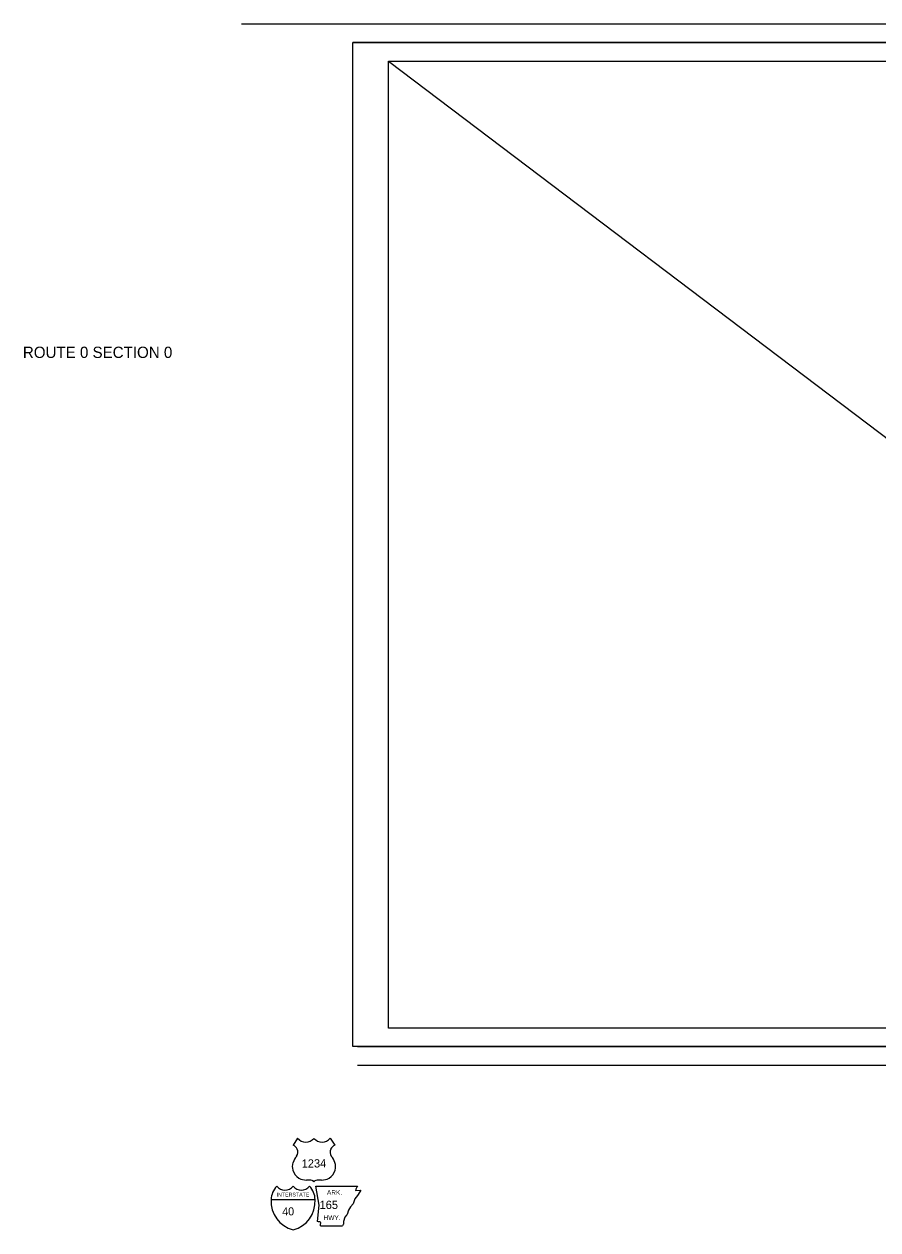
# Model space of a CAD drawing. Extents: x 21307 to 29830, y 1322443 to 1332359.
# Drawn here: x 23110 to 24924, y 1325020 to 1327582 of the extents above; entities that cross this region are included whole.
import ezdxf

# ---------------------------------------------------------------- set-up
doc = ezdxf.new("R2010")
doc.units = 0
doc.layers.add('R_Draft', color=7, linetype='Continuous')
doc.layers.add('R_No Plot', color=7, linetype='Continuous')

msp = doc.modelspace()

# ---------------------------------------------------------------- linework, layer by layer
at = {"layer": 'R_Draft'}
for p, q in [((27081.9, 1327581.7), (23572.1, 1327581.7)), ((27081.9, 1327542.3), (23808.3, 1327542.3)), ((23883.9, 1327502.8), (27045.7, 1327502.8)), ((23883.9, 1325448.4), (23883.9, 1327502.8)), ((27045.7, 1325448.4), (23883.9, 1325448.4)), ((23818.2, 1325409), (27091.7, 1325409)), ((23818.2, 1325369.6), (27091.7, 1325369.6)), ((23691, 1325214.2), (23681.7, 1325199.7)), ((23760.5, 1325214.2), (23769.9, 1325199.7)), ((23730, 1325112.4), (23818.2, 1325112.4)), ((23736.6, 1325072.2), (23730, 1325112.4)), ((23818.1, 1325092.3), (23812.7, 1325085.5)), ((23813.7, 1325103.6), (23825.3, 1325104.3)), ((23822.9, 1325100.5), (23818.1, 1325092.3)), ((23825.3, 1325104.3), (23822.9, 1325100.5)), ((23634.9, 1325084), (23728.2, 1325084)), ((23733.2, 1325037.1), (23736.6, 1325072.2)), ((23803.1, 1325068.4), (23799, 1325061.3)), ((23808.9, 1325074.6), (23803.1, 1325068.4)), ((23810.6, 1325079.4), (23808.9, 1325074.6)), ((23812.7, 1325085.5), (23810.6, 1325079.4)), ((23791.5, 1325046.9), (23788.5, 1325037.7)), ((23795.2, 1325050.7), (23791.5, 1325046.9)), ((23795.1, 1325050.6), (23796, 1325052.1)), ((23799, 1325061.3), (23796, 1325052.1)), ((23739.6, 1325028.5), (23786.1, 1325028.5)), ((23788.4, 1325032.1), (23786.1, 1325028.5)), ((23788.5, 1325037.7), (23788.4, 1325031.8))]:
    msp.add_line(p, q, dxfattribs=at)
for centre, radius, start, end in [((23669.5, 1325178.7), 24.3, 30.7809, 59.9883), ((23708.5, 1325228.8), 22.7, 220.075, 319.6701), ((23743.1, 1325228.8), 22.7, 220.3299, 319.925), ((23782.1, 1325178.7), 24.3, 120.0117, 149.2191), ((23718.4, 1325151), 38.8, 138.9565, 162.6913), ((23674.8, 1325185.1), 16.6, 328.8105, 21.2108), ((23776.8, 1325185.1), 16.6, 158.7892, 211.1895), ((23733.2, 1325151), 38.8, 17.3087, 41.0435), ((23705.5, 1325154.2), 25.7, 160.9576, 197.3819), ((23709.7, 1325154.3), 29.7, 195.1074, 237.1312), ((23741.9, 1325154.3), 29.7, 302.8688, 344.8926), ((23746, 1325154.2), 25.7, 342.6181, 19.0424), ((23710.3, 1325163.6), 38.1, 244.0771, 269.5779), ((23711.2, 1325055.7), 69.8, 81.1942, 90.9539), ((23719.9, 1325118.3), 6.69, 28.0342, 72.9864), ((23731.7, 1325118.3), 6.69, 107.0136, 151.9658), ((23740.4, 1325055.7), 69.8, 89.0461, 98.8058), ((23741.3, 1325163.6), 38.1, 270.4221, 295.9229), ((23675, 1325083.8), 40.1, 134.733, 179.7351), ((23664.2, 1325127), 22.7, 220.075, 319.6701), ((23698.9, 1325127), 22.7, 220.3299, 319.925), ((23688, 1325083.8), 40.1, 0.2649, 45.267), ((23696.9, 1325079.8), 62.1, 176.0938, 255.7023), ((23666.2, 1325079.8), 62.1, 284.2977, 3.9062)]:
    msp.add_arc(centre, radius, start, end, dxfattribs=at)
for points in [[(23818.2, 1325112.4), (23817.1, 1325110.1), (23815.1, 1325107.7), (23814.7, 1325104.3), (23813.7, 1325103.6)], [(23739.6, 1325028.5), (23740, 1325032.3), (23740.3, 1325034.7), (23733.2, 1325037.1)]]:
    msp.add_spline(points, degree=3, dxfattribs=at)
at = {"layer": 'R_No Plot'}
msp.add_line((23883.9, 1327502.8), (25205.3, 1326503), dxfattribs=at)
msp.add_lwpolyline([(23808.3, 1327542.3), (27091.7, 1327542.3), (27091.7, 1325409), (23808.3, 1325409)], close=True, dxfattribs=at)

# ---------------------------------------------------------------- texts
at = {"layer": 'R_Draft'}
for s, height, p in [('ROUTE 0 SECTION 0', 24, (23107.3, 1326872.3)), ('INTERSTATE', 8.1, (23646.4, 1325090.4)), ('ARK.', 10, (23753.4, 1325094.1)), (' 165', 17.56, (23731.2, 1325064)), ('HWY.', 10, (23746.2, 1325040.3))]:
    msp.add_text(s, height=height, dxfattribs=at).set_placement(p)
for s, height, p in [('1234', 17.56, (23699.8, 1325151.6)), (' 40 ', 17, (23652.1, 1325050))]:
    msp.add_text(s, height=height, rotation=1, dxfattribs=at).set_placement(p)

doc.saveas('drawing.dxf')
